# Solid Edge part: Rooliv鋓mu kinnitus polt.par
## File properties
Author: KULL
Template: Iso Metric Part.par
Last saved by: KULL
Revision: 5
Application: Solid Edge
Accuracy: 0,990
Face Style: Model Default
Fill Style: Normal
Coef. of Thermal Exp: 0.0
Thermal Conductivity: 0.0
Specific Heat: 0.0
Modulus of Elasticity: 0.0
Poisson's Ratio: 0.0
Yield Stress: 0.0
Ultimate Stress: 0.0
Elongation: 0.0
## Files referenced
..\..\Rover_ASM.asm
D:\Solid edge leong\Solid edge Sync practice\ROVER_Heiko_Kull_EKSAM\Roolimise_jupid\Roolivõimu silinder.par
imu silinder.par
QD:\Solid edge leong\Solid edge Sync practice\ROVER_Heiko_Kull_EKSAM\Rover_ASM.asm
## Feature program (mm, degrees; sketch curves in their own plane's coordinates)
helix cutout "HelixCutout_1"  NumberOfTurns = 10
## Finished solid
Body 1: sheet body, 2 faces, 26 edges, 22 vertices.
  Faces by surface: plane 2
  Edges by curve: circle 22, line 4
Body 2: solid body, 19 faces, 40 edges, 24 vertices.
  Faces by surface: plane 11, cylinder 3, spline 3, blend 1, torus 1
  Edges by curve: line 24, intersection 7, circle 5, spline 4
Bounding box of the edges (mm; curved faces can reach further): 5.600 x 57.568 x 19.604, from (-17.9, -28.784, 10.4703) to (-12.3, 28.784, 30.0744).
Cylindrical faces by radius (mm): R0.704 x1, R1 x1, R1.4 x1
Toroidal faces (ring radius, tube radius in mm): R1.3 r0.1 x1
Planar faces by outward normal: +x 2, +z 1, -x 2, -y 1, -z 1, oblique 4
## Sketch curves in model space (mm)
circle centre (-17.9, -27.0291, 28.3196) radius 1
circle centre (-16.3, -27.0291, 28.3196) radius 1
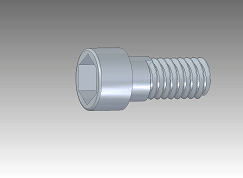
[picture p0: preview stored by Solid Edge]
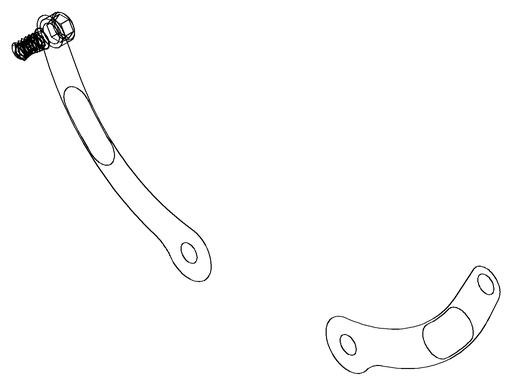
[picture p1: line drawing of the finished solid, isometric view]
